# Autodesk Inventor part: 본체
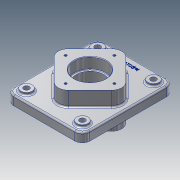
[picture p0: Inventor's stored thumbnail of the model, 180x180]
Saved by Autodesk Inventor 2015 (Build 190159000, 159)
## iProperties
Created: 2026-07
Part Number: 본체
Material: 알루미늄 6061
Document SubType Name: Modeling
Designer: user
Density: 2.7 g/cm^3
Appearance: 알루미늄 - 평지
Mass: 2132.41 g
Surface Area: 955.114 cm^2
Volume: 789.782 cm^3
Author: user
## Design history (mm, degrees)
sketch "스케치1"
  geometry: L1 (-75, 90)-(75, 90); L2 (75, 90)-(75, -90); L3 (75, -90)-(-75, -90); L4 (-75, -90)-(-75, 90); L5 (-75, 90)-(75, -90); L6 (75, 90)-(-75, -90); 1 further point
  constraints: 12 end point, 2 midpoint, 2 parallel, 1 horizontal, 1 perpendicular
  dimensions: "d0" = 150 distance of L2.end L3.end; "d1" = 180 distance of L1.end L2.end
extrude "돌출1" new body sketch "스케치1" distance "d2" = 18; taper "d3" = 0 deg
fillet "모깎기1" dims "d4" = 15
sketch "스케치2"
  geometry: L1 (0, -70.711)-(-70.711, 0); L2 (-70.711, 0)-(0, 70.711); L3 (0, 70.711)-(70.711, 0); L4 (70.711, 0)-(0, -70.711); 2 further points
  constraints: 8 end point, 1 coincident, 1 vertical alignment, 9 other
  dimensions: "d5" = 100 distance of L2.end L3.end
extrude "돌출2" join sketch "스케치2" distance "d6" = 29; taper "d7" = 0 deg; dims "d17" = 41, "d18" = 0
fillet "모깎기2" dims "d8" = 20
fillet "모깎기3" dims "d19" = 20
sketch "스케치3"
  geometry: L1 (0, 0)-(0, 48)
  constraints: 2 end point, 1 vertical
  dimensions: "d9" = 48 distance of L1.start L1.end
hole "구멍1" sketch "스케치3" at (0, 48) diameter "d10" = 4.917; stored, may be unused: countersink angle "d14" = 90 deg, drill point angle "d16" = 118 deg; dims "d11" = 10, "d12" = 4, "d13" = 2, "d15" = 13
hole "구멍2" diameter "d22" = 54; stored, may be unused: countersink angle "d26" = 90 deg, drill point angle "d28" = 0 deg; dims "d20" = 50, "d21" = 50, "d23" = 10, "d24" = 62, "d25" = 22, "d27" = 13
hole "구멍3" diameter "d31" = 62; stored, may be unused: countersink angle "d35" = 90 deg, drill point angle "d37" = 0 deg; dims "d29" = 10, "d30" = 10, "d32" = 10, "d33" = 62, "d34" = 22, "d36" = 22
sketch "스케치5"
  geometry: L1 (-75, -75)-(-75, 75) reference; L2 (-60, 90)-(60, 90) reference; C1 r 11 at (-55, 70); 1 further point
  constraints: 1 centre point
  dimensions: "d41" = 22 diameter of C1; "d42" = 20 distance from line of L1 C1.centre; "d43" = 20 distance from line of C1.centre L2
extrude "돌출3" join sketch "스케치5" distance "d44" = 5; taper "d45" = 0 deg
hole "구멍4" diameter "d48" = 11; stored, may be unused: countersink angle "d52" = 90 deg, drill point angle "d54" = 0 deg; dims "d46" = 10, "d47" = 10, "d49" = 10, "d50" = 62, "d51" = 22, "d53" = 22
sketch "스케치6"
  geometry: L1 (-60, 90)-(60, 90) reference; 2 further points
  constraints: 1 vertical alignment, 1 other
  dimensions: "d61" = 15 distance from line of point (0, 75) L1
feature "엠보싱1" sketch "스케치6" dims "d0" = 150, "d1" = 180, "d62" = 0.5, "d63" = 0
sketch "스케치7"
  geometry: L1 (0, 0)-(0, 48)
  constraints: 2 end point, 1 vertical
  dimensions: "d64" = 48 distance of L1.start L1.end
hole "구멍5" sketch "스케치7" at (0, 48) diameter "d65" = 4.917; stored, may be unused: countersink angle "d69" = 90 deg, drill point angle "d71" = 118 deg; dims "d66" = 10, "d67" = 4, "d68" = 2, "d70" = 13
fillet "모깎기4" dims "d75" = 1
chamfer "모따기1" distance "d76" = 1; stored, may be unused: second distance "d77" = 2, angle "d78" = 45 deg
fillet "모깎기5" dims "d79" = 3
node "솔리드1"
pattern_circular "원형 패턴1" dims angle "d39" = 360 deg
pattern_linear "직사각형 패턴1"
pattern_circular "원형 패턴2" dims angle "d73" = 360 deg
